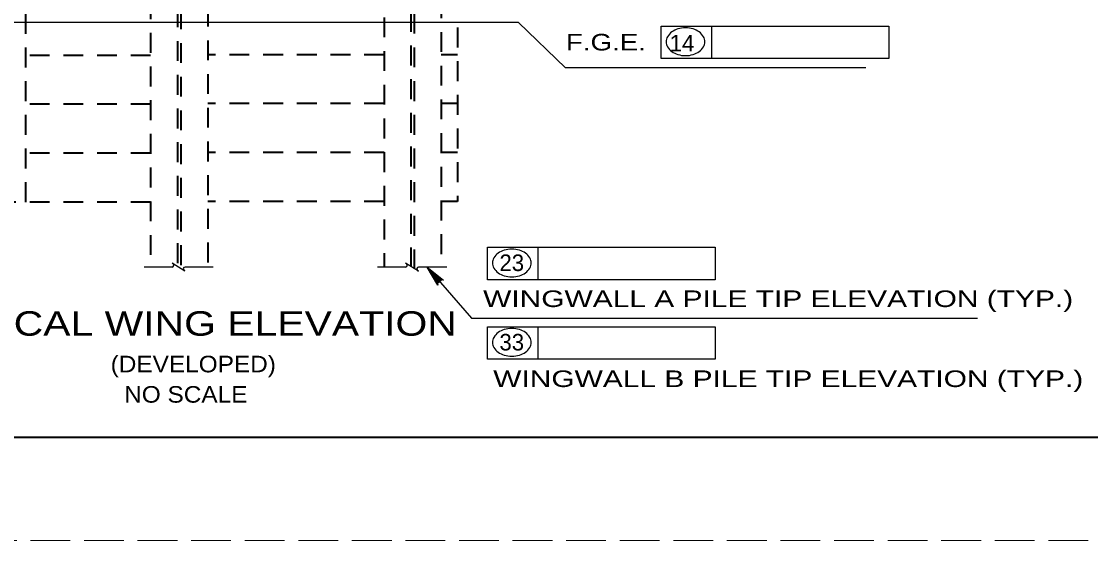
# Model space of a CAD drawing. Extents: x -6.4 to 73.1, y -66 to 0.
# Drawn here: x 51.01 to 58.75, y -66 to -62.24 of the extents above; entities that cross this region are included whole.
import ezdxf
from ezdxf.enums import TextEntityAlignment as Align

# ---------------------------------------------------------------- set-up
doc = ezdxf.new("R2010")
doc.units = 0
doc.header["$LTSCALE"] = 0.048
doc.linetypes.add('LONG_DASHED', pattern=[7.5, 6, -1.5])
doc.linetypes.add('MEDIUM_DASHED', pattern=[4.5, 3, -1.5])
for name, color, linetype, lineweight in [('1', 7, 'Continuous', 13), ('3', 7, 'Continuous', 35), ('4', 7, 'Continuous', 25), ('63', 7, 'LONG_DASHED', 13), ('8', 7, 'Continuous', 25)]:
    doc.layers.add(name, color=color, linetype=linetype, lineweight=lineweight)

msp = doc.modelspace()

# ---------------------------------------------------------------- hatches: boundary and pattern name
at = {"layer": '4'}
msp.add_hatch(color=256, dxfattribs=at).paths.add_polyline_path([(54.02075, -64.13517), (54.04933, -64.11042), (53.96092, -64.03692)])

# ---------------------------------------------------------------- linework, layer by layer
at = {"layer": '1', "lineweight": 35}
msp.add_lwpolyline([(35.75, -65.25), (67.25, -65.25), (67.25, -44.75), (35.75, -44.75)], close=True, dxfattribs=at)
at = {"layer": '3', "linetype": 'MEDIUM_DASHED'}
for p, q in [((54.16433, -61.06375), (54.16433, -63.54408)), ((54.04625, -61.09708), (54.04625, -64.00233)), ((53.63283, -61.23483), (53.63283, -64.01342)), ((52.35583, -61.64542), (52.35583, -64.00233)), ((51.94242, -61.835), (51.94242, -64.01342)), ((51.03858, -63.54892), (51.03858, -62.06967)), ((51.94242, -62.48592), (51.03858, -62.48592)), ((53.63283, -62.48108), (52.35583, -62.48108)), ((54.16433, -62.48108), (54.04625, -62.48108)), ((51.94242, -62.84025), (51.03858, -62.84025)), ((53.63283, -62.83542), (52.35583, -62.83542)), ((54.16433, -62.83542), (54.04625, -62.83542)), ((51.94242, -63.19458), (51.03858, -63.19458)), ((53.63283, -63.18975), (52.35583, -63.18975)), ((54.16433, -63.18975), (54.04625, -63.18975)), ((51.94242, -63.54892), (50.65467, -63.54892)), ((53.63283, -63.54408), (52.35583, -63.54408)), ((54.16433, -63.54408), (54.04625, -63.54408))]:
    msp.add_line(p, q, dxfattribs=at)
at = {"layer": '4'}
for p, q in [((54.60633, -62.247), (50.78325, -62.247)), ((54.60633, -62.247), (54.94717, -62.57542)), ((55.64075, -62.27342), (57.28917, -62.27342)), ((55.64075, -62.50967), (55.64075, -62.27342)), ((56.00767, -62.50967), (56.00767, -62.27342)), ((57.28917, -62.27342), (57.28917, -62.50967)), ((57.28917, -62.50967), (55.64075, -62.50967)), ((57.12075, -62.57542), (54.94717, -62.57542)), ((54.38283, -63.8755), (56.03117, -63.8755)), ((54.38283, -64.11175), (54.38283, -63.8755)), ((54.74967, -64.11175), (54.74967, -63.8755)), ((56.03117, -63.8755), (56.03117, -64.11175)), ((53.94525, -64.01875), (54.26508, -64.38933)), ((56.03117, -64.11175), (54.38283, -64.11175)), ((54.26508, -64.38933), (57.93, -64.38933)), ((54.38283, -64.45067), (56.03117, -64.45067)), ((54.38283, -64.68692), (54.38283, -64.45067)), ((54.74967, -64.68692), (54.74967, -64.45067)), ((56.03117, -64.45067), (56.03117, -64.68692)), ((56.03117, -64.68692), (54.38283, -64.68692))]:
    msp.add_line(p, q, dxfattribs=at)
msp.add_lwpolyline([(53.94525, -64.01875), (54.06383, -64.11342), (54.05033, -64.10992), (54.03892, -64.11192), (54.03017, -64.11717), (54.02375, -64.125), (54.02, -64.136), (54.0215, -64.14992), (53.94525, -64.01875), (54.02, -64.136), (54.02375, -64.125), (53.94525, -64.01875), (54.03017, -64.11717), (54.03892, -64.11192), (53.94525, -64.01875), (54.05033, -64.10992)], dxfattribs=at)
msp.add_lwpolyline([(54.02075, -64.13517), (54.04933, -64.11042), (53.96092, -64.03692)], close=True, dxfattribs=at)
for centre, radius, start, end in [((55.78105, -62.4059), 0.1103, 125.63164, 149.97668), ((55.80211, -62.43529), 0.14646, 106.53583, 125.63164), ((55.81589, -62.48169), 0.19487, 90, 106.53583), ((55.81589, -62.48169), 0.19487, 73.46417, 90), ((55.82967, -62.43529), 0.14646, 54.36836, 73.46417), ((55.85074, -62.4059), 0.1103, 30.02332, 54.36836), ((55.74884, -62.38728), 0.07309, 149.97668, 180), ((55.74884, -62.38728), 0.07309, 180, 210.02332), ((55.88295, -62.38728), 0.07309, 0, 30.02332), ((55.88295, -62.38728), 0.07309, 329.97668, 0), ((55.78105, -62.36867), 0.1103, 210.02332, 234.36836), ((55.80211, -62.33927), 0.14646, 234.36836, 253.46417), ((55.81589, -62.29287), 0.19487, 253.46417, 270), ((55.81589, -62.29287), 0.19487, 270, 286.53583), ((55.82967, -62.33927), 0.14646, 286.53583, 305.63164), ((55.85074, -62.36867), 0.1103, 305.63164, 329.97668), ((54.49087, -63.98934), 0.07309, 149.97668, 180), ((54.52308, -64.00795), 0.1103, 125.63164, 149.97668), ((54.54415, -64.03734), 0.14646, 106.53583, 125.63164), ((54.55792, -64.08375), 0.19487, 90, 106.53583), ((54.55792, -64.08375), 0.19487, 73.46417, 90), ((54.5717, -64.03734), 0.14646, 54.36836, 73.46417), ((54.59277, -64.00795), 0.1103, 30.02332, 54.36836), ((54.62498, -63.98934), 0.07309, 0, 30.02332), ((54.49087, -63.98934), 0.07309, 180, 210.02332), ((54.52308, -63.97072), 0.1103, 210.02332, 234.36836), ((54.59277, -63.97072), 0.1103, 305.63164, 329.97668), ((54.62498, -63.98934), 0.07309, 329.97668, 0), ((54.54415, -63.94133), 0.14646, 234.36836, 253.46417), ((54.55792, -63.89492), 0.19487, 253.46417, 270), ((54.55792, -63.89492), 0.19487, 270, 286.53583), ((54.5717, -63.94133), 0.14646, 286.53583, 305.63164), ((54.52308, -64.58313), 0.1103, 125.63164, 149.97668), ((54.54415, -64.61252), 0.14646, 106.53583, 125.63164), ((54.55792, -64.65893), 0.19487, 90, 106.53583), ((54.55792, -64.65893), 0.19487, 73.46417, 90), ((54.5717, -64.61252), 0.14646, 54.36836, 73.46417), ((54.59277, -64.58313), 0.1103, 30.02332, 54.36836), ((54.49087, -64.56452), 0.07309, 149.97668, 180), ((54.49087, -64.56452), 0.07309, 180, 210.02332), ((54.62498, -64.56452), 0.07309, 0, 30.02332), ((54.62498, -64.56452), 0.07309, 329.97668, 0), ((54.52308, -64.5459), 0.1103, 210.02332, 234.36836), ((54.54415, -64.51651), 0.14646, 234.36836, 253.46417), ((54.55792, -64.47011), 0.19487, 253.46417, 270), ((54.55792, -64.47011), 0.19487, 270, 286.53583), ((54.5717, -64.51651), 0.14646, 286.53583, 305.63164), ((54.59277, -64.5459), 0.1103, 305.63164, 329.97668)]:
    msp.add_arc(centre, radius, start, end, dxfattribs=at)
at = {"layer": '63'}
msp.add_lwpolyline([(34, -66), (68, -66), (68, -44), (34, -44)], close=True, dxfattribs=at)
at = {"layer": '8', "linetype": 'MEDIUM_DASHED', "lineweight": 35}
for p, q in [((52.13733, -59.69858), (52.13733, -64.01408)), ((52.16092, -59.71267), (52.16092, -64.02892)), ((53.82775, -60.7065), (53.82775, -64.01408)), ((53.85133, -60.72058), (53.85133, -64.02892))]:
    msp.add_line(p, q, dxfattribs=at)
at = {"layer": '8'}
for p, q in [((52.09858, -64.01875), (51.89467, -64.01875)), ((52.39592, -64.01875), (52.19183, -64.01875)), ((53.78908, -64.01875), (53.58508, -64.01875)), ((54.08633, -64.01875), (53.88233, -64.01875))]:
    msp.add_line(p, q, dxfattribs=at)
for points in [[(52.185, -64.04417), (52.19083, -64.04775), (52.09842, -63.98967), (52.10458, -63.99358)], [(53.8755, -64.04417), (53.88125, -64.04775), (53.78892, -63.98967), (53.79508, -63.99358)]]:
    msp.add_lwpolyline(points, dxfattribs=at)
for centre, start, end in [((52.09738, -64.00514), 275.32859, 57.86724), ((52.19189, -64.03236), 90, 240), ((53.78783, -64.00514), 275.32859, 57.86724), ((53.88234, -64.03236), 90, 240)]:
    msp.add_arc(centre, 0.01364, start, end, dxfattribs=at)

# ---------------------------------------------------------------- texts
at = {"layer": '4'}
for s, width, p in [('F.G.E.', 1.25, (54.94975, -62.45033)), ('WINGWALL A PILE TIP ELEVATION (TYP.)', 1.35, (54.35008, -64.30842)), ('WINGWALL B PILE TIP ELEVATION (TYP.)', 1.35, (54.42308, -64.88767))]:
    msp.add_text(s, height=0.12, dxfattribs=dict(at, width=width)).set_placement(p)
for s, p in [('14', (55.79029, -62.45725)), ('23', (54.55763, -64.04783)), ('33', (54.55763, -64.623))]:
    msp.add_text(s, height=0.12, dxfattribs=at).set_placement(p, align=Align.CENTER)
for s, height, width, p in [('TYPICAL WING ELEVATION', 0.1772, 1.25, (52.22583, -64.51617)), ('(DEVELOPED)', 0.12, 1.1, (52.25104, -64.78125)), ('NO SCALE', 0.12, 1.1, (52.19696, -65.001))]:
    msp.add_text(s, height=height, dxfattribs=dict(at, width=width)).set_placement(p, align=Align.CENTER)

doc.saveas('drawing.dxf')
